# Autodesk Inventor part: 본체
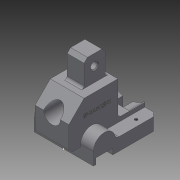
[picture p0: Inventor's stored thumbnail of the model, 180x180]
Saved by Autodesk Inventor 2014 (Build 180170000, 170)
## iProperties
Created: 2016-11
Part Number: 본체
Material: 일반
Document SubType Name: Modeling
Designer: USER
Density: 1 g/cm^3
Appearance: 기본값
Author: USER
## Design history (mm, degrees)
sketch "스케치2"
  geometry: L1 (0, 0)-(3, 0); L2 (3, 0)-(3, 7); L3 (3, 7)-(23, 7); L4 (23, 7)-(23, 0); L5 (23, 0)-(76, 0); L6 (76, 15)-(0, 15); L7 (76, 0)-(76, 15); L8 (13, 7)-(13, 15); L9 (0, 15)-(0, 0); A1 r 13 centre (13, 15) between (26, 15) and (0, 15)
  constraints: 18 end point, 4 parallel, 3 perpendicular, 2 point on circle, 2 point on line, 1 centre point, 1 coincident, 1 horizontal, 1 horizontal alignment, 1 midpoint, 1 tangent
  dimensions: "d9" = 20 distance between parallel lines of L4 L2; "d10" = 7 distance between parallel lines of L1 L3; "d11" = 15 distance between parallel lines of L1 L6; "d13" = 26 diameter of A1; "d14" = 76 distance between parallel lines of L9 L7
extrude "돌출1" new body sketch "스케치2" distance "d15" = 15; taper "d16" = 0 deg
node "작업 평면6"
  node "작업 평면5"
sketch "스케치5"
  geometry: 1 further point
sketch "스케치6"
  geometry: L1 (-60, -14)-(-12, -14); L2 (-12, -14)-(-12, 44); L3 (-12, 44)-(-60, 44); L4 (-60, 44)-(-60, -14); L5 (0, 76)-(-15, 76) reference; L6 (0, 0)-(0, 3) reference
  constraints: 8 end point, 2 parallel, 1 horizontal, 1 perpendicular
  dimensions: "d28" = 90 distance between parallel lines of L5 L1; "d29" = 60 distance between parallel lines of L4 L6; "d30" = 58 distance of L3.end L1.start; "d31" = 48 distance of L1.start L1.end
extrude "돌출3" join sketch "스케치6" stored distance "d32" = 40; taper "d33" = 0 deg
fillet "모깎기1" dims "d34" = 5
sketch "스케치7"
  geometry: L1 (0, 0)-(40, 0) reference; L2 (40, 60)-(55, 60) reference; C1 r 14.5 at (20, 18); 1 further point
  constraints: 1 centre point, 1 midpoint, 1 vertical alignment
  dimensions: "d35" = 42 distance from line of L2 C1.centre; "d36" = 29 diameter of C1
extrude "돌출4" cut sketch "스케치7" distance "d37" = 7; taper "d38" = 0 deg
sketch "스케치8"
  geometry: C1 r 14.5 at (0, 0) reference; C2 r 10 at (0, 0); 1 further point
  constraints: 1 centre point, 1 coincident
  dimensions: "d39" = 20 diameter of C2
extrude "돌출5" cut sketch "스케치8" stored distance "d40" = 7; taper "d41" = 0 deg
chamfer "모따기1" distance "d42" = 1; stored, may be unused: second distance "d43" = 2, angle "d44" = 45 deg
sketch "스케치9"
  geometry: L1 (-60, 44)-(-60, -14) reference; L2 (-60, -14)-(-12, -14) reference; L3 (-42, -14)-(-60, -14); L4 (-60, 4)-(-60, -14); L5 (-60, 4)-(-42, -14); 1 further point
  constraints: 6 end point, 2 collinear, 2 point on line
  dimensions: "d45" = 45 deg angle of L1 L5; "d46" = 18 distance from line of L4.start L2
extrude "돌출6" cut sketch "스케치9" stored distance "d47" = 7; taper "d48" = 0 deg
chamfer "모따기2" distance "d49" = 4; stored, may be unused: second distance "d50" = 2, angle "d51" = 45 deg
chamfer "모따기3" distance "d52" = 5; stored, may be unused: second distance "d53" = 2, angle "d54" = 45 deg
node "작업 평면9"
sketch "스케치13"
  geometry: L1 (-55, 0)-(-55, 15) reference; L2 (-40, 0)-(-40, 15) reference; L3 (-40, 15)-(-55, 15) reference; L4 (-40, 0)-(-55, 0) reference; L5 (15, 15)-(0, 15) reference; L6 (0, 0)-(0, 15) reference; L7 (15, 15)-(15, 0) reference; L8 (0, 0)-(15, 0) reference; L9 (15, 15)-(-55, 15); L10 (-55, 15)-(-55, 0); L11 (-55, 0)-(15, 0); L12 (15, 0)-(15, 15)
  constraints: 8 end point, 2 parallel, 1 horizontal, 1 perpendicular
extrude "돌출8" join sketch "스케치13" distance "d59" = 3; taper "d60" = 0 deg
sketch "스케치16"
  geometry: L1 (0, -5)-(-40, -5); L2 (-40, -5)-(-40, 15); L3 (-40, 15)-(0, 15); L4 (0, 15)-(0, -5); L5 (-55, 15)-(15, 15) reference; 3 further points
  constraints: 8 end point, 3 midpoint, 2 parallel, 1 coincident, 1 horizontal, 1 perpendicular, 1 vertical alignment
  dimensions: "d63" = 20 distance between parallel lines of L3 L1; "d64" = 40 distance of L1.start L1.end
extrude "돌출10" join sketch "스케치16" stored distance "d65" = 18; taper "d66" = 0 deg
sketch "스케치17"
  geometry: L1 (50, -20)-(10, -20) reference; C1 r 14.5 at (30, -42) reference; A1 r 29 centre (30, -42) between (48.894, -20) and (11.106, -20); 1 further point
  constraints: 2 point on circle, 2 point on line, 1 centre point, 1 coincident
  dimensions: "d67" = 58 diameter of A1
extrude "돌출11" cut sketch "스케치17" distance "d68" = 18; taper "d69" = 0 deg
sketch "스케치18"
  geometry: L1 (50, -20)-(48.894, -20) reference; L2 (0, 0)-(60, 0) reference; L3 (11.106, -20)-(10, -20) reference; L4 (36, -13.627)-(36, 0); L5 (24, -13.627)-(24, 0); L6 (36, 0)-(24, 0); A1 r 29 centre (30, -42) between (48.894, -20) and (11.106, -20) reference; A2 r 29 centre (30, -42) between (36, -13.627) and (24, -13.627); 2 further points
  constraints: 8 end point, 4 point on circle, 2 perpendicular, 2 point on line, 1 centre point, 1 coincident, 1 collinear, 1 concentric, 1 midpoint, 1 vertical alignment
  dimensions: "d70" = 12 distance between parallel lines of L5 L4
extrude "돌출12" cut sketch "스케치18" stored distance "d71" = 18; taper "d72" = 0 deg
fillet "모깎기2" dims "d73" = 3
node "작업 평면10"
sketch "스케치20"
  geometry: L1 (45, -9)-(25, -9); L2 (25, -9)-(25, 16); L3 (25, 16)-(45, 16); L4 (45, 16)-(45, -9); L5 (55, 21)-(15, 21) reference; L6 (55, -19)-(55, 21) reference; L7 (55, -19)-(15, -19) reference; L8 (15, 21)-(15, -19) reference; L9 (55, 21)-(15, 21) reference; L10 (55, -19)-(55, 21) reference; 5 further points
  constraints: 8 end point, 4 midpoint, 2 parallel, 1 horizontal, 1 perpendicular, 1 vertical alignment
  dimensions: "d77" = 25 distance of L3.end L1.start; "d78" = 20 distance of L1.start L1.end; "d117" = 5 distance between parallel lines of L5 L3
extrude "돌출13" join sketch "스케치20" stored distance "d79" = 18; taper "d80" = 0 deg
fillet "모깎기3" dims "d81" = 3
chamfer "모따기4" distance "d82" = 4; stored, may be unused: second distance "d83" = 2, angle "d84" = 45 deg
sketch "스케치21"
  geometry: L1 (-30, 7)-(-30, 24) reference; L2 (60, 12)-(60, 60) reference; C1 r 4 at (-17, 15.5); 2 further points
  constraints: 1 centre point, 1 horizontal alignment, 1 midpoint
  dimensions: "d85" = 8 diameter of C1; "d86" = 77 distance from line of L2 C1.centre
extrude "돌출14" cut sketch "스케치21" stored distance "d87" = 18; taper "d88" = 0 deg
chamfer "모따기5" distance "d89" = 1; stored, may be unused: second distance "d90" = 2, angle "d91" = 45 deg
chamfer "모따기6" distance "d92" = 1; stored, may be unused: second distance "d93" = 2, angle "d94" = 45 deg
sketch "스케치22"
  geometry: L1 (-23, 44)-(-60, 44) reference; L2 (-60, 44)-(-60, 4) reference; 2 further points
  constraints: 1 other
  dimensions: "d95" = 25 distance from line of L1 point (-42, 19); "d96" = 18 distance from line of L2 point (-42, 19)
extrude "돌출15" join sketch "스케치22" distance "d97" = 0.5; taper "d98" = 0 deg
sketch "스케치23"
  geometry: L1 (0, 45.708)-(10, 45.708) reference; L2 (-1.106, 27.708)-(-38.894, 27.708) reference; L3 (-20, 27.708)-(-20, 47.383); 2 further points
  constraints: 2 end point, 1 midpoint, 1 perpendicular
  dimensions: "d99" = 18 distance from line of point (7.5, 27.708) L1; "d100" = 27.5 distance from line of L3 point (7.5, 27.708)
sketch "스케치24"
  geometry: L1 (15, 45.708)-(5, 45.708) reference; L2 (53.894, 27.708)-(16.106, 27.708) reference; L3 (35, 27.708)-(35, 47.631); 2 further points
  constraints: 2 end point, 1 midpoint, 1 perpendicular
  dimensions: "d101" = 18 distance from line of L1 point (7.5, 27.708); "d102" = 27.5 distance from line of L3 point (7.5, 27.708)
hole "구멍1" sketch "스케치24" at (7.5, 27.708) diameter "d103" = 3.459; stored, may be unused: countersink angle "d107" = 90 deg, drill point angle "d109" = 118 deg; dims "d104" = 6, "d105" = 4, "d106" = 2, "d108" = 100
hole "구멍2" sketch "스케치23" diameter "d110" = 3.459; stored, may be unused: countersink angle "d114" = 90 deg, drill point angle "d116" = 118 deg; dims "d111" = 6, "d112" = 4, "d113" = 2, "d115" = 100
node "솔리드1"
mirror "대칭2"
node "투영된 루프6"
other parameters: "d58" = -3
